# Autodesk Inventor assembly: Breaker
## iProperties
Author: t8558es
Created: 2004-01
Part Number: Breaker
Document SubType Name: Assembly
Designer: t8558es
Control State: 0
Master: False
Checked Out: False
PropertySet Name: Design Tracking Control
Shininess: 64.0
Angle Display Precision: 2
Document Length Units: 11272
Document Angle Units: 11286
Document Time Units: 11279
Document Mass Units: 11290
Document Length Units Precision: 3
Document Angle Units Precision: 2
Compacted: False
PropertySet Name: _Private Model Information
Density: 0.0
Volumn: 0.0
Area: 0.0
PropertySet Name: Model Information
